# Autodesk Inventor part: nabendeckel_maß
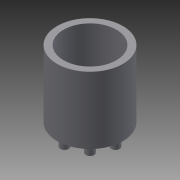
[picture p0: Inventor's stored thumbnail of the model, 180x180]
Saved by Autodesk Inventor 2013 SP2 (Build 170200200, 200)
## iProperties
Created: 2020-05
Part Number: nabendeckel_maß
Material: Allgemein
Document SubType Name: Modeling
Designer: Admin
Density: 1 g/cm^3
Author: Admin
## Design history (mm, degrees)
sketch "Skizze1"
  geometry: C1 r 5.9 at (0, 0); 1 further point
  constraints: 1 centre point, 1 coincident
  dimensions: "d0" = 11.8 diameter of C1
extrude "Extrusion1" new body sketch "Skizze1" distance "d1" = 12; taper "d2" = 0 deg
sketch "Skizze2"
  geometry: C1 r 5.9 at (0, 0) reference; C2 r 4.75 at (0, 0)
  constraints: 1 centre point, 1 coincident
  dimensions: "d3" = 9.5 diameter of C2
extrude "Extrusion2" cut sketch "Skizze2" distance "d4" = 9; taper "d5" = 0 deg
sketch "Skizze3"
  geometry: L1 (0, 5.9)-(0, -5.9); L2 (-5.9, 0)-(5.9, 0); L3 (0, 0)-(-3.238, 3.238); L4 (0, 0)-(3.238, 3.238); L5 (0, 0)-(4.579, 0); L6 (0, 0)-(3.238, -3.238); L7 (0, 0)-(-3.238, -3.238); C1 r 0.75 at (-3.238, 3.238); C2 r 0.75 at (0, 4.579); C3 r 0.75 at (-4.579, 0); C4 r 0.75 at (-3.238, -3.238); C5 r 0.75 at (0, -4.579); C6 r 0.75 at (3.238, -3.238); C7 r 0.75 at (4.579, 0); C8 r 0.75 at (3.238, 3.238); C9 r 3 at (0, 0); A1 r 5.9 centre (0, 0) between (0, 5.9) and (0, -5.9) reference
  constraints: 14 end point, 9 centre point, 7 coincident, 4 point on circle, 3 perpendicular, 3 point on line, 1 equal length, 1 horizontal, 1 vertical, 9 other
  dimensions: "d6" = 45 deg angle of L1 L3; "d7" = 45 deg angle of L5 L4; "d8" = 1.5 diameter of C1; "d9" = 1.5 diameter of C2; "d10" = 1.5 diameter of C3; "d11" = 1.5 diameter of C4; "d12" = 1.5 diameter of C5; "d13" = 1.5 diameter of C6; "d14" = 1.5 diameter of C7; "d15" = 1.5 diameter of C8; "d16" = 6 diameter of C9
extrude "Extrusion3" join sketch "Skizze3" distance "d17" = 1.5; taper "d18" = 0 deg
sketch "Skizze4"
  geometry: C1 r 5.9 at (0, 0) reference; C2 r 3 at (0, 0)
  constraints: 1 centre point, 1 coincident
  dimensions: "d19" = 6 diameter of C2
extrude "Extrusion4" join sketch "Skizze4" distance "d20" = 2; taper "d21" = 0 deg
node "Volumenkörper1"
